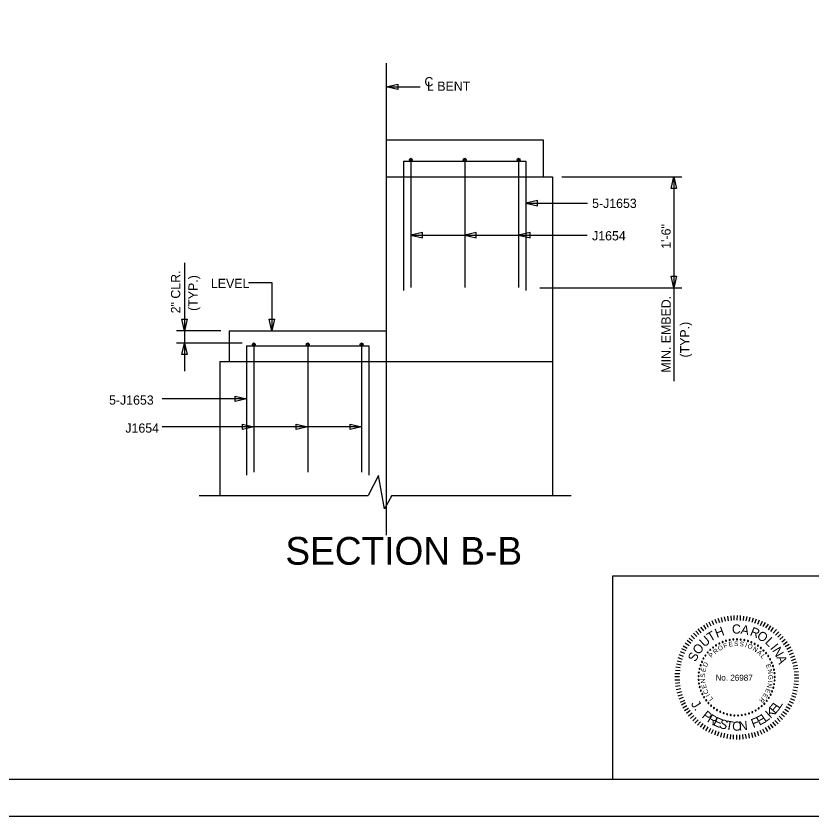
# Model space of a CAD drawing. Extents: x 1970675.2 to 1970711.3, y 796145.2 to 796167.2.
# Drawn here: x 1970689.79 to 1970700.56, y 796145.25 to 796156.08 of the extents above; entities that cross this region are included whole.
import ezdxf

# ---------------------------------------------------------------- set-up
doc = ezdxf.new("R2010")
doc.units = 0
for name, color, linetype in [('BR_AUTO DIMENSION', 7, 'Continuous'), ('BR_BORDER LINES', 7, 'Continuous'), ('BR_CENTER LINES', 7, 'Continuous'), ('BR_CONCRETE', 7, 'Continuous'), ('BR_REBAR', 7, 'Continuous'), ('BR_TEXT', 7, 'Continuous'), ('Default', 7, 'Continuous'), ('Level 31', 7, 'Continuous')]:
    doc.layers.add(name, color=color, linetype=linetype)

msp = doc.modelspace()

# ---------------------------------------------------------------- linework, layer by layer
at = {"layer": 'BR_AUTO DIMENSION'}
for p, q in [((1970694.8, 796155.118), (1970695.26, 796155.118)), ((1970697.178, 796153.898), (1970698.802, 796153.898)), ((1970698.695, 796153.898), (1970698.695, 796151.132)), ((1970696.691, 796153.54), (1970697.525, 796153.54)), ((1970695.134, 796153.107), (1970697.522, 796153.107)), ((1970695.863, 796153.107), (1970695.943, 796153.107)), ((1970696.863, 796153.107), (1970696.943, 796153.107)), ((1970692.072, 796152.733), (1970692.072, 796151.268)), ((1970692.935, 796152.466), (1970693.252, 796152.466)), ((1970693.252, 796152.466), (1970693.252, 796151.816)), ((1970696.88, 796152.398), (1970698.802, 796152.398)), ((1970692.561, 796151.816), (1970691.962, 796151.816)), ((1970692.849, 796151.649), (1970691.962, 796151.649)), ((1970692.91, 796150.893), (1970691.768, 796150.893)), ((1970694.467, 796150.513), (1970691.768, 796150.513)), ((1970693.738, 796150.513), (1970693.658, 796150.513))]:
    msp.add_line(p, q, dxfattribs=at)
for points in [[(1970694.956, 796155.082), (1970694.8, 796155.118), (1970694.956, 796155.154)], [(1970698.659, 796153.742), (1970698.695, 796153.898), (1970698.731, 796153.742)], [(1970696.847, 796153.576), (1970696.691, 796153.54), (1970696.847, 796153.504)], [(1970695.29, 796153.143), (1970695.134, 796153.107), (1970695.29, 796153.071)], [(1970696.019, 796153.143), (1970695.863, 796153.107), (1970696.019, 796153.071)], [(1970696.748, 796153.143), (1970696.592, 796153.107), (1970696.748, 796153.071)], [(1970698.731, 796152.554), (1970698.695, 796152.398), (1970698.659, 796152.554)], [(1970692.108, 796151.972), (1970692.072, 796151.816), (1970692.036, 796151.972)], [(1970693.288, 796151.972), (1970693.252, 796151.816), (1970693.216, 796151.972)], [(1970692.036, 796151.493), (1970692.072, 796151.649), (1970692.108, 796151.493)], [(1970692.754, 796150.929), (1970692.91, 796150.893), (1970692.754, 796150.857)], [(1970692.853, 796150.549), (1970693.009, 796150.513), (1970692.853, 796150.477)], [(1970693.582, 796150.549), (1970693.738, 796150.513), (1970693.582, 796150.477)], [(1970694.311, 796150.549), (1970694.467, 796150.513), (1970694.311, 796150.477)]]:
    msp.add_lwpolyline(points, close=True, dxfattribs=at)
at = {"layer": 'BR_BORDER LINES'}
for p, q in [((1970697.87, 796148.496), (1970703.236, 796148.496)), ((1970697.87, 796145.746), (1970697.87, 796148.496)), ((1970677.07, 796145.746), (1970710.736, 796145.746))]:
    msp.add_line(p, q, dxfattribs=at)
at = {"layer": 'BR_CENTER LINES'}
msp.add_line((1970694.8, 796155.437), (1970694.8, 796149.049), dxfattribs=at)
at = {"layer": 'BR_CONCRETE'}
for p, q in [((1970694.8, 796154.399), (1970694.8, 796151.398)), ((1970694.8, 796154.399), (1970696.925, 796154.399)), ((1970696.925, 796154.399), (1970696.925, 796153.898)), ((1970694.8, 796153.898), (1970697.05, 796153.898)), ((1970697.05, 796153.898), (1970697.05, 796151.398)), ((1970692.675, 796151.816), (1970692.675, 796151.398)), ((1970692.675, 796151.816), (1970694.8, 796151.816)), ((1970692.55, 796151.398), (1970692.55, 796149.586)), ((1970692.55, 796151.398), (1970697.05, 796151.398)), ((1970697.05, 796151.398), (1970697.05, 796149.586))]:
    msp.add_line(p, q, dxfattribs=at)
at = {"layer": 'BR_REBAR'}
for p, q in [((1970695.035, 796154.11), (1970695.035, 796152.36)), ((1970695.035, 796154.11), (1970696.691, 796154.11)), ((1970695.134, 796154.149), (1970695.134, 796152.399)), ((1970695.863, 796154.149), (1970695.863, 796152.399)), ((1970696.592, 796154.149), (1970696.592, 796152.399)), ((1970696.691, 796154.11), (1970696.691, 796152.36)), ((1970692.91, 796151.61), (1970692.91, 796149.86)), ((1970692.91, 796151.61), (1970694.566, 796151.61)), ((1970693.009, 796151.649), (1970693.009, 796149.899)), ((1970693.738, 796151.649), (1970693.738, 796149.899)), ((1970694.467, 796151.649), (1970694.467, 796149.899)), ((1970694.566, 796151.61), (1970694.566, 796149.86))]:
    msp.add_line(p, q, dxfattribs=at)
for centre in [(1970695.134, 796154.13), (1970695.863, 796154.13), (1970696.592, 796154.13), (1970693.009, 796151.63), (1970693.738, 796151.63), (1970694.467, 796151.63)]:
    msp.add_circle(centre, 0.0195, dxfattribs=at)
at = {"layer": 'BR_TEXT'}
for p, q in [((1970699.237, 796147.833), (1970699.213, 796147.889)), ((1970699.275, 796147.85), (1970699.255, 796147.908)), ((1970699.315, 796147.862), (1970699.293, 796147.92)), ((1970699.351, 796147.872), (1970699.338, 796147.933)), ((1970699.392, 796147.882), (1970699.378, 796147.941)), ((1970699.432, 796147.889), (1970699.423, 796147.95)), ((1970699.472, 796147.893), (1970699.468, 796147.954)), ((1970699.511, 796147.896), (1970699.512, 796147.96)), ((1970699.553, 796147.898), (1970699.554, 796147.96)), ((1970699.595, 796147.895), (1970699.597, 796147.959)), ((1970699.635, 796147.892), (1970699.64, 796147.953)), ((1970699.674, 796147.887), (1970699.685, 796147.948)), ((1970699.714, 796147.879), (1970699.728, 796147.938)), ((1970699.755, 796147.869), (1970699.771, 796147.93)), ((1970699.792, 796147.858), (1970699.814, 796147.915)), ((1970699.832, 796147.845), (1970699.854, 796147.903)), ((1970699.867, 796147.827), (1970699.895, 796147.883)), ((1970699.065, 796147.728), (1970699.025, 796147.778)), ((1970699.099, 796147.753), (1970699.06, 796147.804)), ((1970699.13, 796147.774), (1970699.099, 796147.829)), ((1970699.165, 796147.798), (1970699.135, 796147.852)), ((1970699.2, 796147.816), (1970699.174, 796147.872)), ((1970699.903, 796147.81), (1970699.935, 796147.866)), ((1970699.941, 796147.792), (1970699.973, 796147.845)), ((1970699.974, 796147.767), (1970700.008, 796147.821)), ((1970700.008, 796147.746), (1970700.044, 796147.796)), ((1970698.973, 796147.645), (1970698.93, 796147.688)), ((1970699.003, 796147.676), (1970698.959, 796147.72)), ((1970699.032, 796147.703), (1970698.991, 796147.748)), ((1970700.04, 796147.72), (1970700.081, 796147.769)), ((1970700.071, 796147.695), (1970700.115, 796147.739)), ((1970700.1, 796147.667), (1970700.143, 796147.71)), ((1970700.128, 796147.636), (1970700.175, 796147.677)), ((1970698.901, 796147.551), (1970698.847, 796147.584)), ((1970698.922, 796147.58), (1970698.873, 796147.62)), ((1970698.948, 796147.614), (1970698.899, 796147.653)), ((1970700.155, 796147.604), (1970700.201, 796147.642)), ((1970700.179, 796147.57), (1970700.228, 796147.609)), ((1970700.201, 796147.541), (1970700.253, 796147.573)), ((1970698.841, 796147.444), (1970698.784, 796147.469)), ((1970698.859, 796147.481), (1970698.802, 796147.508)), ((1970698.876, 796147.515), (1970698.822, 796147.547)), ((1970700.223, 796147.504), (1970700.276, 796147.535)), ((1970700.24, 796147.469), (1970700.298, 796147.496)), ((1970700.258, 796147.432), (1970700.315, 796147.457)), ((1970698.799, 796147.329), (1970698.738, 796147.344)), ((1970698.812, 796147.365), (1970698.75, 796147.388)), ((1970698.824, 796147.405), (1970698.766, 796147.427)), ((1970700.275, 796147.393), (1970700.332, 796147.414)), ((1970700.288, 796147.353), (1970700.346, 796147.375)), ((1970698.781, 796147.251), (1970698.721, 796147.259)), ((1970698.792, 796147.287), (1970698.729, 796147.303)), ((1970700.298, 796147.317), (1970700.359, 796147.331)), ((1970700.307, 796147.275), (1970700.367, 796147.29)), ((1970700.315, 796147.239), (1970700.374, 796147.246)), ((1970698.774, 796147.171), (1970698.709, 796147.171)), ((1970698.772, 796147.129), (1970698.709, 796147.13)), ((1970698.777, 796147.21), (1970698.715, 796147.217)), ((1970700.321, 796147.197), (1970700.382, 796147.204)), ((1970700.323, 796147.158), (1970700.383, 796147.157)), ((1970698.773, 796147.086), (1970698.709, 796147.085)), ((1970698.775, 796147.048), (1970698.714, 796147.041)), ((1970700.32, 796147.035), (1970700.381, 796147.027)), ((1970700.322, 796147.074), (1970700.382, 796147.071)), ((1970700.325, 796147.117), (1970700.386, 796147.116)), ((1970698.779, 796147.007), (1970698.718, 796146.998)), ((1970698.789, 796146.967), (1970698.727, 796146.954)), ((1970698.796, 796146.925), (1970698.735, 796146.911)), ((1970700.295, 796146.913), (1970700.355, 796146.897)), ((1970700.304, 796146.955), (1970700.364, 796146.94)), ((1970700.313, 796146.994), (1970700.372, 796146.984)), ((1970698.808, 796146.888), (1970698.746, 796146.867)), ((1970698.819, 796146.849), (1970698.761, 796146.828)), ((1970698.836, 796146.812), (1970698.778, 796146.785)), ((1970700.253, 796146.801), (1970700.309, 796146.773)), ((1970700.27, 796146.837), (1970700.327, 796146.815)), ((1970700.284, 796146.876), (1970700.342, 796146.854)), ((1970698.853, 796146.776), (1970698.796, 796146.746)), ((1970698.87, 796146.739), (1970698.816, 796146.708)), ((1970698.894, 796146.702), (1970698.839, 796146.671)), ((1970700.194, 796146.691), (1970700.246, 796146.659)), ((1970700.216, 796146.728), (1970700.269, 796146.696)), ((1970700.235, 796146.765), (1970700.292, 796146.734)), ((1970698.915, 796146.673), (1970698.865, 796146.636)), ((1970698.94, 796146.639), (1970698.89, 796146.6)), ((1970698.965, 796146.605), (1970698.921, 796146.564)), ((1970700.119, 796146.596), (1970700.166, 796146.554)), ((1970700.147, 796146.629), (1970700.193, 796146.589)), ((1970700.171, 796146.662), (1970700.22, 796146.625)), ((1970698.994, 796146.579), (1970698.949, 796146.534)), ((1970699.023, 796146.549), (1970698.98, 796146.503)), ((1970699.055, 796146.523), (1970699.014, 796146.476)), ((1970699.088, 796146.497), (1970699.049, 796146.449)), ((1970699.119, 796146.475), (1970699.088, 796146.423)), ((1970699.997, 796146.489), (1970700.033, 796146.441)), ((1970700.03, 796146.515), (1970700.07, 796146.467)), ((1970700.062, 796146.54), (1970700.104, 796146.494)), ((1970700.09, 796146.57), (1970700.133, 796146.524)), ((1970699.154, 796146.453), (1970699.123, 796146.399)), ((1970699.188, 796146.433), (1970699.161, 796146.377)), ((1970699.225, 796146.415), (1970699.201, 796146.36)), ((1970699.263, 796146.398), (1970699.242, 796146.341)), ((1970699.303, 796146.385), (1970699.28, 796146.327)), ((1970699.339, 796146.373), (1970699.325, 796146.314)), ((1970699.38, 796146.366), (1970699.365, 796146.304)), ((1970699.743, 796146.37), (1970699.758, 796146.31)), ((1970699.78, 796146.381), (1970699.801, 796146.323)), ((1970699.82, 796146.393), (1970699.841, 796146.336)), ((1970699.856, 796146.41), (1970699.883, 796146.354)), ((1970699.892, 796146.427), (1970699.922, 796146.371)), ((1970699.93, 796146.446), (1970699.961, 796146.392)), ((1970699.964, 796146.468), (1970699.997, 796146.416)), ((1970699.419, 796146.354), (1970699.409, 796146.296)), ((1970699.459, 796146.35), (1970699.454, 796146.288)), ((1970699.498, 796146.347), (1970699.498, 796146.285)), ((1970699.54, 796146.344), (1970699.54, 796146.283)), ((1970699.582, 796146.346), (1970699.584, 796146.284)), ((1970699.623, 796146.348), (1970699.626, 796146.286)), ((1970699.661, 796146.352), (1970699.671, 796146.294)), ((1970699.702, 796146.363), (1970699.715, 796146.301))]:
    msp.add_line(p, q, dxfattribs=at)
for centre, start, end in [((1970699.265, 796147.557), 32.7576, 212.7576), ((1970699.265, 796147.557), 212.7576, 32.7576), ((1970699.309, 796147.581), 27.2191, 207.2191), ((1970699.309, 796147.581), 207.2191, 27.2191), ((1970699.354, 796147.602), 21.6807, 201.6807), ((1970699.354, 796147.602), 201.6807, 21.6807), ((1970699.401, 796147.618), 16.1422, 196.1422), ((1970699.401, 796147.618), 196.1422, 16.1422), ((1970699.45, 796147.629), 10.6038, 190.6038), ((1970699.45, 796147.629), 190.6038, 10.6038), ((1970699.499, 796147.636), 5.0653, 185.0653), ((1970699.499, 796147.636), 185.0653, 5.0653), ((1970699.549, 796147.638), 359.5268, 179.5268), ((1970699.549, 796147.638), 179.5268, 359.5268), ((1970699.599, 796147.635), 353.9884, 173.9884), ((1970699.599, 796147.635), 173.9884, 353.9884), ((1970699.648, 796147.627), 348.4499, 168.4499), ((1970699.648, 796147.627), 168.4499, 348.4499), ((1970699.696, 796147.615), 342.9114, 162.9114), ((1970699.696, 796147.615), 162.9114, 342.9114), ((1970699.743, 796147.598), 337.373, 157.373), ((1970699.743, 796147.598), 157.373, 337.373), ((1970699.788, 796147.576), 151.8345, 331.8345), ((1970699.788, 796147.576), 331.8345, 151.8345), ((1970699.831, 796147.551), 326.2961, 146.2961), ((1970699.153, 796147.459), 49.373, 229.373), ((1970699.153, 796147.459), 229.373, 49.373), ((1970699.187, 796147.495), 43.8345, 223.8345), ((1970699.187, 796147.495), 223.8345, 43.8345), ((1970699.225, 796147.528), 38.2961, 218.2961), ((1970699.225, 796147.528), 218.2961, 38.2961), ((1970699.831, 796147.551), 146.2961, 326.2961), ((1970699.871, 796147.521), 140.7576, 320.7576), ((1970699.871, 796147.521), 320.7576, 140.7576), ((1970699.907, 796147.488), 135.2191, 315.2191), ((1970699.907, 796147.488), 315.2191, 135.2191), ((1970699.941, 796147.451), 129.6807, 309.6807), ((1970699.941, 796147.451), 309.6807, 129.6807), ((1970699.073, 796147.333), 65.9884, 245.9884), ((1970699.073, 796147.333), 245.9884, 65.9884), ((1970699.095, 796147.378), 60.4499, 240.4499), ((1970699.095, 796147.378), 240.4499, 60.4499), ((1970699.122, 796147.42), 54.9114, 234.9114), ((1970699.122, 796147.42), 234.9114, 54.9114), ((1970699.971, 796147.411), 124.1422, 304.1422), ((1970699.971, 796147.411), 304.1422, 124.1422), ((1970699.997, 796147.368), 118.6038, 298.6038), ((1970699.997, 796147.368), 298.6038, 118.6038), ((1970699.041, 796147.239), 77.0653, 257.0653), ((1970699.041, 796147.239), 257.0653, 77.0653), ((1970699.055, 796147.287), 71.5268, 251.5268), ((1970699.055, 796147.287), 251.5268, 71.5268), ((1970700.018, 796147.323), 113.0653, 293.0653), ((1970700.018, 796147.323), 293.0653, 113.0653), ((1970700.036, 796147.277), 107.5268, 287.5268), ((1970700.036, 796147.277), 287.5268, 107.5268), ((1970700.048, 796147.228), 101.9884, 281.9884), ((1970700.048, 796147.228), 281.9884, 101.9884), ((1970699.028, 796147.14), 88.1422, 268.1422), ((1970699.032, 796147.19), 82.6038, 262.6038), ((1970699.028, 796147.14), 268.1422, 88.1422), ((1970699.032, 796147.19), 262.6038, 82.6038), ((1970700.056, 796147.179), 96.4499, 276.4499), ((1970700.059, 796147.129), 90.9114, 270.9114), ((1970700.056, 796147.179), 276.4499, 96.4499), ((1970700.059, 796147.129), 270.9114, 90.9114), ((1970699.029, 796147.09), 93.6807, 273.6807), ((1970699.034, 796147.041), 99.2191, 279.2191), ((1970699.029, 796147.09), 273.6807, 93.6807), ((1970699.034, 796147.041), 279.2191, 99.2191), ((1970700.051, 796147.03), 79.8345, 259.8345), ((1970700.057, 796147.08), 85.373, 265.373), ((1970700.051, 796147.03), 259.8345, 79.8345), ((1970700.057, 796147.08), 265.373, 85.373), ((1970699.045, 796146.992), 104.7576, 284.7576), ((1970699.045, 796146.992), 284.7576, 104.7576), ((1970699.059, 796146.944), 110.2961, 290.2961), ((1970699.059, 796146.944), 290.2961, 110.2961), ((1970699.079, 796146.898), 295.8345, 115.8345), ((1970700.024, 796146.934), 68.7576, 248.7576), ((1970700.024, 796146.934), 248.7576, 68.7576), ((1970700.04, 796146.982), 74.2961, 254.2961), ((1970700.04, 796146.982), 254.2961, 74.2961), ((1970699.079, 796146.898), 115.8345, 295.8345), ((1970699.103, 796146.855), 121.373, 301.373), ((1970699.103, 796146.855), 301.373, 121.373), ((1970699.131, 796146.813), 126.9114, 306.9114), ((1970699.131, 796146.813), 306.9114, 126.9114), ((1970699.95, 796146.805), 52.1422, 232.1422), ((1970699.95, 796146.805), 232.1422, 52.1422), ((1970699.979, 796146.846), 57.6807, 237.6807), ((1970699.979, 796146.846), 237.6807, 57.6807), ((1970700.003, 796146.889), 63.2191, 243.2191), ((1970700.003, 796146.889), 243.2191, 63.2191), ((1970699.162, 796146.775), 132.4499, 312.4499), ((1970699.162, 796146.775), 312.4499, 132.4499), ((1970699.198, 796146.74), 137.9884, 317.9884), ((1970699.198, 796146.74), 317.9884, 137.9884), ((1970699.236, 796146.708), 143.5268, 323.5268), ((1970699.236, 796146.708), 323.5268, 143.5268), ((1970699.842, 796146.702), 35.5268, 215.5268), ((1970699.842, 796146.702), 215.5268, 35.5268), ((1970699.882, 796146.733), 41.0653, 221.0653), ((1970699.882, 796146.733), 221.0653, 41.0653), ((1970699.918, 796146.767), 46.6038, 226.6038), ((1970699.918, 796146.767), 226.6038, 46.6038), ((1970699.278, 796146.68), 149.0653, 329.0653), ((1970699.278, 796146.68), 329.0653, 149.0653), ((1970699.321, 796146.657), 154.6038, 334.6038), ((1970699.321, 796146.657), 334.6038, 154.6038), ((1970699.367, 796146.638), 160.1422, 340.1422), ((1970699.367, 796146.638), 340.1422, 160.1422), ((1970699.415, 796146.623), 345.6807, 165.6807), ((1970699.415, 796146.623), 165.6807, 345.6807), ((1970699.464, 796146.613), 351.2191, 171.2191), ((1970699.464, 796146.613), 171.2191, 351.2191), ((1970699.513, 796146.607), 356.7576, 176.7576), ((1970699.513, 796146.607), 176.7576, 356.7576), ((1970699.563, 796146.607), 2.2961, 182.2961), ((1970699.563, 796146.607), 182.2961, 2.2961), ((1970699.613, 796146.611), 7.8345, 187.8345), ((1970699.613, 796146.611), 187.8345, 7.8345), ((1970699.662, 796146.62), 13.373, 193.373), ((1970699.662, 796146.62), 193.373, 13.373), ((1970699.71, 796146.634), 18.9114, 198.9114), ((1970699.71, 796146.634), 198.9114, 18.9114), ((1970699.756, 796146.652), 24.4499, 204.4499), ((1970699.756, 796146.652), 204.4499, 24.4499), ((1970699.8, 796146.675), 29.9884, 209.9884), ((1970699.8, 796146.675), 209.9884, 29.9884)]:
    msp.add_arc(centre, 0.00701, start, end, dxfattribs=at)
at = {"layer": 'Default'}
for p, q in [((1970692.27, 796149.586), (1970694.555, 796149.586)), ((1970694.878, 796149.586), (1970697.303, 796149.586))]:
    msp.add_line(p, q, dxfattribs=at)
msp.add_lwpolyline([(1970694.878, 796149.586), (1970694.779, 796149.404), (1970694.694, 796149.856), (1970694.555, 796149.586)], dxfattribs=at)
at = {"layer": 'Level 31'}
msp.add_lwpolyline([(1970675.236, 796167.246), (1970675.236, 796145.246), (1970711.236, 796145.246), (1970711.236, 796167.246)], dxfattribs=at)

# ---------------------------------------------------------------- texts
at = {"layer": 'BR_AUTO DIMENSION'}
for s, rotation, p in [('C', 360, (1970695.318, 796155.123)), ('L BENT', 360, (1970695.353, 796155.063)), ('1\'-6"', 90, (1970698.651, 796152.925)), ('2" CLR.', 90, (1970692.012, 796152.051)), ('(TYP.)', 90, (1970692.249, 796152.084)), ('LEVEL', 360, (1970692.428, 796152.393)), ('MIN. EMBED.', 90, (1970698.651, 796151.247)), ('(TYP.)', 90, (1970698.904, 796151.453))]:
    msp.add_text(s, height=0.125, rotation=rotation, dxfattribs=at).set_placement(p)
for s, p in [('5-J1653', (1970697.587, 796153.477)), ('J1654', (1970697.587, 796153.038)), ('5-J1653', (1970691.049, 796150.814)), ('J1654', (1970691.27, 796150.435))]:
    msp.add_text(s, height=0.125, dxfattribs=at).set_placement(p)
at = {"layer": 'BR_TEXT'}
for s, height, rotation, p in [('SECTION B-B', 0.375, 360, (1970693.436, 796148.648)), ('H', 0.124, 20.3637, (1970699.276, 796147.657)), ('C', 0.124, 359.5482, (1970699.48, 796147.716)), ('A', 0.124, 348.1981, (1970699.592, 796147.716)), ('R', 0.124, 337.4344, (1970699.715, 796147.696)), ('U', 0.124, 40.8022, (1970699.107, 796147.525)), ('T', 0.124, 30.4992, (1970699.188, 796147.6)), ('O', 0.124, 326.5869, (1970699.807, 796147.66)), ('L', 0.124, 315.9488, (1970699.92, 796147.592)), ('O', 0.124, 52.0267, (1970699.032, 796147.421)), ('F', 0.0622, 20.6127, (1970699.377, 796147.514)), ('E', 0.0622, 11.4103, (1970699.442, 796147.536)), ('S', 0.0622, 2.208, (1970699.51, 796147.547)), ('S', 0.0622, 352.6608, (1970699.581, 796147.547)), ('I', 0.0622, 343.1136, (1970699.652, 796147.535)), ('O', 0.0622, 338.4392, (1970699.685, 796147.525)), ('I', 0.124, 308.6613, (1970699.991, 796147.518)), ('S', 0.124, 63.2511, (1970698.987, 796147.325)), ('P', 0.0622, 49.9421, (1970699.206, 796147.382)), ('R', 0.0622, 40.3949, (1970699.254, 796147.434)), ('O', 0.0622, 30.8477, (1970699.31, 796147.478)), ('N', 0.0622, 328.2042, (1970699.755, 796147.493)), ('A', 0.0622, 318.657, (1970699.814, 796147.453)), ('N', 0.124, 300.7037, (1970700.022, 796147.488)), ('L', 0.0622, 309.4546, (1970699.863, 796147.406)), ('A', 0.124, 289.4792, (1970700.081, 796147.395)), ('E', 0.0622, 78.2388, (1970699.122, 796147.19)), ('D', 0.0622, 69.0364, (1970699.139, 796147.257)), ('E', 0.0622, 291.049, (1970699.937, 796147.291)), ('N', 0.0622, 281.8466, (1970699.96, 796147.226)), ('S', 0.0622, 87.786, (1970699.116, 796147.119)), ('No. 26987', 0.0817, 359.5268, (1970699.257, 796147.08)), ('G', 0.0622, 272.2995, (1970699.971, 796147.155)), ('N', 0.0622, 97.3332, (1970699.122, 796147.048)), ('E', 0.0622, 106.5355, (1970699.14, 796146.981)), ('N', 0.0622, 257.7339, (1970699.966, 796147.047)), ('I', 0.0622, 262.4084, (1970699.971, 796147.081)), ('C', 0.0622, 116.4266, (1970699.169, 796146.914)), ('E', 0.0622, 238.9844, (1970699.92, 796146.915)), ('E', 0.0622, 248.1867, (1970699.948, 796146.978)), ('J', 0.124, 302.9559, (1970698.92, 796146.763)), ('I', 0.0622, 121.1011, (1970699.187, 796146.884)), ('L', 0.0622, 129.9595, (1970699.228, 796146.832)), ('R', 0.0622, 229.782, (1970699.883, 796146.858)), ('.', 0.124, 309.3974, (1970698.964, 796146.695)), ('K', 0.124, 42.3031, (1970700.001, 796146.561)), ('E', 0.124, 49.3639, (1970700.066, 796146.621)), ('L', 0.124, 56.4247, (1970700.124, 796146.689)), ('P', 0.124, 321.1035, (1970699.063, 796146.586)), ('R', 0.124, 328.5359, (1970699.136, 796146.528)), ('E', 0.124, 335.9684, (1970699.216, 796146.48)), ('F', 0.124, 21.1206, (1970699.768, 796146.435)), ('E', 0.124, 28.1814, (1970699.851, 796146.467)), ('L', 0.124, 35.2422, (1970699.929, 796146.51)), ('S', 0.124, 343.0292, (1970699.297, 796146.444)), ('T', 0.124, 350.4617, (1970699.387, 796146.418)), ('O', 0.124, 358.1419, (1970699.482, 796146.403)), ('N', 0.124, 5.8221, (1970699.579, 796146.401))]:
    msp.add_text(s, height=height, rotation=rotation, dxfattribs=at).set_placement(p)

doc.saveas('drawing.dxf')
